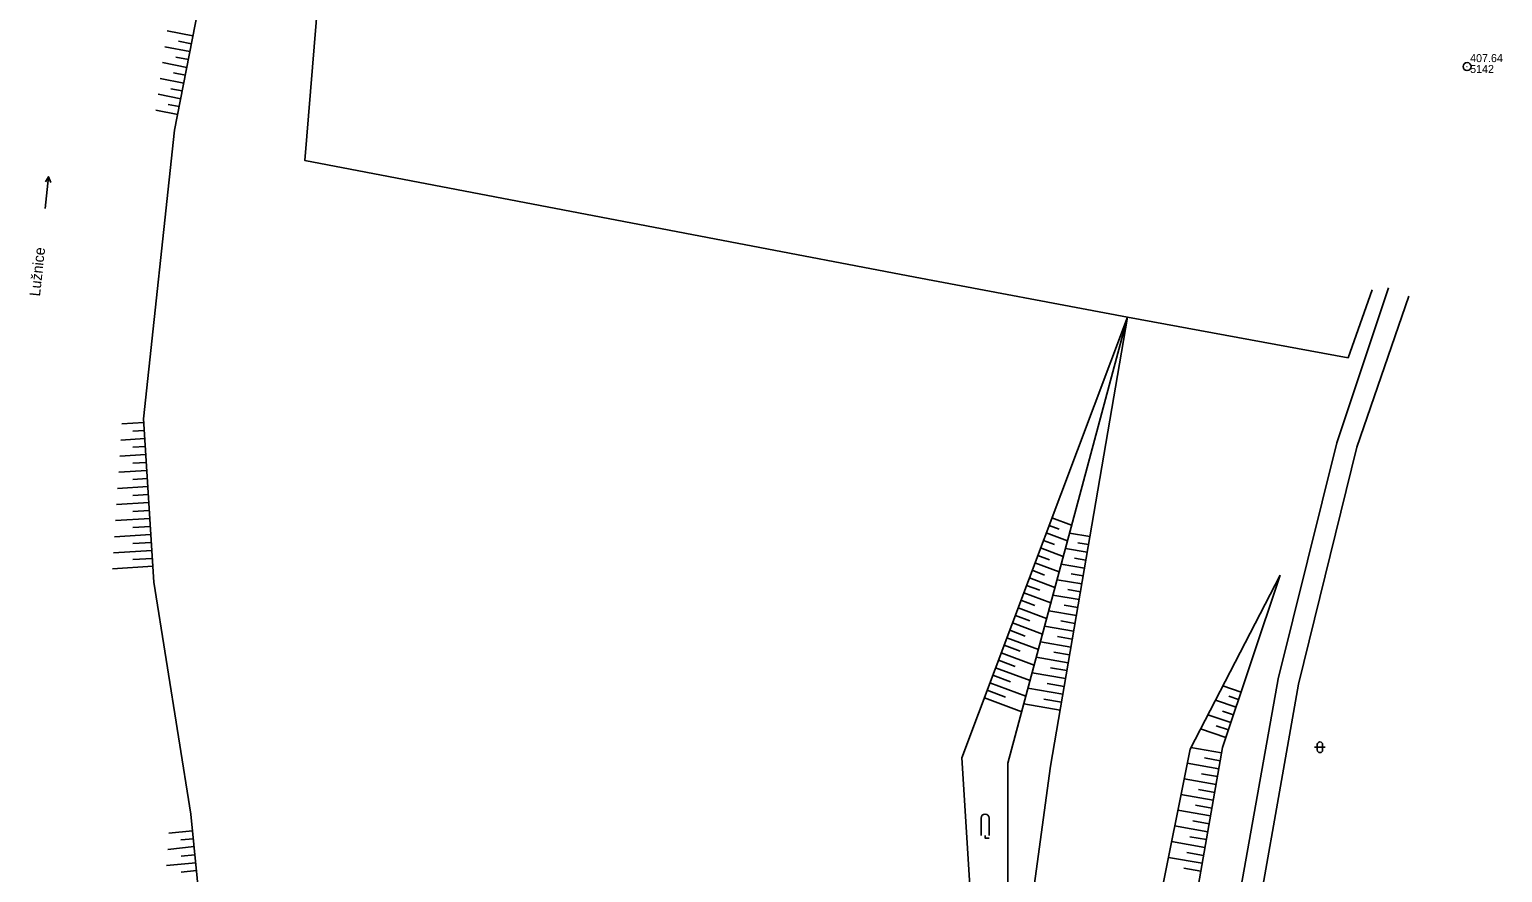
# Model space of a CAD drawing. Extents: x -737488 to -734267, y -1145775 to -1142573.
# Drawn here: x -735046 to -734907.9, y -1143003.1 to -1142924.1 of the extents above; entities that cross this region are included whole.
import ezdxf

# ---------------------------------------------------------------- set-up
doc = ezdxf.new("R2010")
doc.units = 0
for name, color, linetype in [('Vrstva 1', 7, 'Continuous'), ('Vrstva 10', 7, 'Continuous'), ('Vrstva 12', 7, 'Continuous'), ('Vrstva 13', 7, 'Continuous'), ('Vrstva 19', 7, 'Continuous'), ('Vrstva 3', 7, 'Continuous'), ('Vrstva 9', 7, 'Continuous')]:
    doc.layers.add(name, color=color, linetype=linetype)

# ---------------------------------------------------------------- blocks, each defined once
blk = doc.blocks.new('1.079')
at = {"layer": 'Vrstva 1'}
for radius in [0.75, 0.001]:
    blk.add_circle((0, -0.001), radius, dxfattribs=at)
blk = doc.blocks.new('3.100')
at = {"layer": 'Vrstva 1'}
for p, q in [((-0.75, 0), (-0.75, 3.25)), ((0.75, 0), (0.75, 3.25))]:
    blk.add_line(p, q, dxfattribs=at)
blk.add_lwpolyline([(0, 0), (0, -0.5), (0.75, -0.5)], dxfattribs=at)
blk.add_arc((0, 3.25), 0.75, 0, 180, dxfattribs=at)
blk = doc.blocks.new('3.160')
at = {"layer": 'Vrstva 1'}
for p, q in [((-1, 0), (1, 0)), ((-0.5, -0.5), (-0.5, 0.5)), ((0.5, -0.5), (0.5, 0.5))]:
    blk.add_line(p, q, dxfattribs=at)
for centre, start, end in [((0, 0.5), 0, 180), ((0, -0.5), 180, 360)]:
    blk.add_arc(centre, 0.5, start, end, dxfattribs=at)
blk = doc.blocks.new('8.021')
at = {"layer": 'Vrstva 1'}
blk.add_line((-3, 0), (3, 0), dxfattribs=at)
blk.add_lwpolyline([(2, 0.5), (3, 0), (2, -0.5)], dxfattribs=at)

msp = doc.modelspace()

# ---------------------------------------------------------------- linework, layer by layer
at = {"layer": 'Vrstva 10'}
for points in [[(-734923.42, -1142962.8), (-734918.58, -1142948.28)], [(-734916.69, -1142949.06), (-734921.55, -1142963.22)], [(-734928.93, -1142984.91), (-734923.42, -1142962.8)], [(-734921.55, -1142963.22), (-734927.04, -1142985.42)], [(-734934.2, -1143014.49), (-734928.93, -1142984.91)], [(-734927.04, -1142985.42), (-734932.25, -1143014.98)]]:
    msp.add_lwpolyline(points, dxfattribs=at)
at = {"layer": 'Vrstva 12'}
for points in [[(-735032.35, -1142933.5), (-735024.58, -1142893.71)], [(-735030.63, -1142924.67), (-735033.06, -1142924.19)], [(-735030.77, -1142925.4), (-735031.97, -1142925.17)], [(-735030.91, -1142926.14), (-735033.27, -1142925.68)], [(-735031.06, -1142926.88), (-735032.22, -1142926.65)], [(-735031.2, -1142927.61), (-735033.48, -1142927.17)], [(-735031.34, -1142928.35), (-735032.46, -1142928.13)], [(-735031.49, -1142929.08), (-735033.69, -1142928.65)], [(-735031.63, -1142929.82), (-735032.71, -1142929.61)], [(-735031.78, -1142930.56), (-735033.9, -1142930.14)], [(-735031.92, -1142931.29), (-735032.96, -1142931.09)], [(-735032.06, -1142932.03), (-735034.11, -1142931.63)], [(-735035.26, -1142960.56), (-735032.35, -1142933.5)], [(-734958.58, -1142992.32), (-734943.06, -1142951.01)], [(-734943.06, -1142951.01), (-734954.25, -1142992.81)], [(-734950.26, -1142993.11), (-734943.06, -1142951.01)], [(-735035.24, -1142960.9), (-735037.29, -1142961.03)], [(-735034.29, -1142975.87), (-735035.26, -1142960.56)], [(-735035.14, -1142962.4), (-735037.39, -1142962.54)], [(-735035.19, -1142961.65), (-735036.27, -1142961.72)], [(-735035.05, -1142963.89), (-735037.49, -1142964.05)], [(-735035.1, -1142963.15), (-735036.27, -1142963.22)], [(-735034.95, -1142965.39), (-735037.59, -1142965.56)], [(-735035, -1142964.64), (-735036.27, -1142964.72)], [(-735034.86, -1142966.89), (-735037.69, -1142967.07)], [(-735034.91, -1142966.14), (-735036.27, -1142966.23)], [(-735034.76, -1142968.39), (-735037.79, -1142968.58)], [(-735034.81, -1142967.64), (-735036.28, -1142967.73)], [(-735034.72, -1142969.13), (-735036.28, -1142969.23)], [(-735034.67, -1142969.88), (-735037.89, -1142970.09)], [(-735034.62, -1142970.63), (-735036.28, -1142970.74)], [(-734950.4, -1142970.54), (-734949.44, -1142970.9)], [(-734950.13, -1142969.84), (-734948.29, -1142970.53)], [(-735034.58, -1142971.38), (-735037.98, -1142971.6)], [(-735034.53, -1142972.13), (-735036.28, -1142972.24)], [(-734950.93, -1142971.95), (-734949.9, -1142972.33)], [(-734950.66, -1142971.24), (-734948.68, -1142971.99)], [(-734946.58, -1142971.59), (-734948.48, -1142971.26)], [(-734946.71, -1142972.32), (-734947.69, -1142972.16)], [(-735034.48, -1142972.88), (-735038.08, -1142973.1)], [(-735034.43, -1142973.63), (-735036.28, -1142973.74)], [(-734951.45, -1142973.35), (-734950.36, -1142973.76)], [(-734951.19, -1142972.65), (-734949.07, -1142973.44)], [(-734946.83, -1142973.06), (-734948.87, -1142972.72)], [(-734946.96, -1142973.8), (-734948.01, -1142973.62)], [(-735034.39, -1142974.37), (-735038.18, -1142974.61)], [(-734951.98, -1142974.75), (-734950.82, -1142975.19)], [(-734951.72, -1142974.05), (-734949.46, -1142974.9)], [(-734947.08, -1142974.54), (-734949.26, -1142974.17)], [(-734947.21, -1142975.28), (-734948.33, -1142975.09)], [(-734928.73, -1142975.2), (-734937.19, -1142991.51)], [(-734934.15, -1142991.37), (-734928.73, -1142975.2)], [(-735030.82, -1142997.59), (-735034.29, -1142975.87)], [(-734952.51, -1142976.16), (-734951.27, -1142976.62)], [(-734952.24, -1142975.46), (-734949.85, -1142976.36)], [(-734947.34, -1142976.02), (-734949.65, -1142975.63)], [(-734947.46, -1142976.76), (-734948.65, -1142976.56)], [(-734953.04, -1142977.56), (-734951.73, -1142978.05)], [(-734952.77, -1142976.86), (-734950.24, -1142977.81)], [(-734947.59, -1142977.5), (-734950.04, -1142977.08)], [(-734947.72, -1142978.24), (-734948.98, -1142978.02)], [(-734953.56, -1142978.97), (-734952.19, -1142979.48)], [(-734953.3, -1142978.26), (-734950.63, -1142979.27)], [(-734947.84, -1142978.98), (-734950.43, -1142978.54)], [(-734954.09, -1142980.37), (-734952.65, -1142980.91)], [(-734953.83, -1142979.67), (-734951.02, -1142980.72)], [(-734948.1, -1142980.46), (-734950.82, -1142979.99)], [(-734947.97, -1142979.72), (-734949.3, -1142979.49)], [(-734954.62, -1142981.77), (-734953.11, -1142982.34)], [(-734954.35, -1142981.07), (-734951.4, -1142982.18)], [(-734948.35, -1142981.94), (-734951.21, -1142981.45)], [(-734948.22, -1142981.2), (-734949.62, -1142980.96)], [(-734955.15, -1142983.18), (-734953.57, -1142983.77)], [(-734954.88, -1142982.48), (-734951.79, -1142983.64)], [(-734948.6, -1142983.41), (-734951.6, -1142982.9)], [(-734948.48, -1142982.67), (-734949.94, -1142982.42)], [(-734955.67, -1142984.58), (-734954.03, -1142985.2)], [(-734955.41, -1142983.88), (-734952.18, -1142985.09)], [(-734948.85, -1142984.89), (-734951.99, -1142984.36)], [(-734948.73, -1142984.15), (-734950.26, -1142983.89)], [(-734956.2, -1142985.99), (-734954.48, -1142986.63)], [(-734955.94, -1142985.28), (-734952.57, -1142986.55)], [(-734949.11, -1142986.37), (-734952.38, -1142985.81)], [(-734948.98, -1142985.63), (-734950.58, -1142985.36)], [(-734932.4, -1142986.16), (-734934.12, -1142985.58)], [(-734956.46, -1142986.69), (-734952.96, -1142988)], [(-734949.36, -1142987.85), (-734952.77, -1142987.27)], [(-734949.23, -1142987.11), (-734950.9, -1142986.82)], [(-734932.88, -1142987.58), (-734934.81, -1142986.93)], [(-734932.64, -1142986.87), (-734933.55, -1142986.56)], [(-734933.36, -1142989), (-734935.51, -1142988.28)], [(-734933.12, -1142988.29), (-734934.14, -1142987.95)], [(-734933.83, -1142990.42), (-734936.21, -1142989.62)], [(-734933.59, -1142989.71), (-734934.73, -1142989.33)], [(-734937.19, -1142991.51), (-734946.11, -1143036.08)], [(-734941.65, -1143034.14), (-734934.15, -1142991.37)], [(-734934.24, -1142991.86), (-734937.11, -1142991.36)], [(-734957.7, -1143006.28), (-734958.58, -1142992.32)], [(-734954.25, -1142992.81), (-734954.27, -1143006.77)], [(-734952.18, -1143007.07), (-734950.26, -1142993.11)], [(-734934.5, -1142993.34), (-734937.45, -1142992.82)], [(-734934.37, -1142992.6), (-734935.84, -1142992.34)], [(-734934.75, -1142994.82), (-734937.75, -1142994.29)], [(-734934.63, -1142994.08), (-734936.11, -1142993.82)], [(-734935.01, -1142996.3), (-734938.04, -1142995.76)], [(-734934.88, -1142995.56), (-734936.39, -1142995.29)], [(-734935.27, -1142997.77), (-734938.34, -1142997.24)], [(-734935.14, -1142997.03), (-734936.67, -1142996.77)], [(-735029.64, -1143009.61), (-735030.82, -1142997.59)], [(-734935.53, -1142999.25), (-734938.63, -1142998.71)], [(-734935.4, -1142998.51), (-734936.94, -1142998.24)], [(-735030.67, -1142999.16), (-735032.9, -1142999.38)], [(-735030.59, -1142999.91), (-735031.77, -1143000.02)], [(-734935.79, -1143000.73), (-734938.93, -1143000.18)], [(-734935.66, -1142999.99), (-734937.22, -1142999.72)], [(-735030.52, -1143000.65), (-735033, -1143000.9)], [(-735030.45, -1143001.4), (-735031.75, -1143001.53)], [(-734935.92, -1143001.47), (-734937.5, -1143001.19)], [(-735030.37, -1143002.15), (-735033.11, -1143002.41)], [(-735030.3, -1143002.89), (-735031.73, -1143003.03)], [(-734936.05, -1143002.21), (-734939.22, -1143001.65)], [(-734936.18, -1143002.94), (-734937.77, -1143002.66)]]:
    msp.add_lwpolyline(points, dxfattribs=at)
at = {"layer": 'Vrstva 9'}
msp.add_lwpolyline([(-735008.81, -1142850.65), (-735008.6, -1142854.61), (-735010.4, -1142862.01), (-735012.24, -1142865.68), (-735016.95, -1142897.52), (-735020.15, -1142936.34), (-734980.3, -1142943.95), (-734962.94, -1142947.26), (-734943.06, -1142951.01), (-734922.38, -1142954.83), (-734920.11, -1142948.45)], dxfattribs=at)

# ---------------------------------------------------------------- block references
at = {"layer": 'Vrstva 1', "xscale": 0.5, "yscale": 0.5}
msp.add_blockref('1.079', (-734911.22, -1142927.54), dxfattribs=at)
at = {"layer": 'Vrstva 3', "xscale": 0.4999999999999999, "yscale": 0.5, "rotation": 83.86187116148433}
msp.add_blockref('8.021', (-735044.32, -1142939.36), dxfattribs=at)
at = {"layer": 'Vrstva 3', "xscale": 0.5, "yscale": 0.5}
for name, p in [('3.160', (-734925.01, -1142991.34)), ('3.100', (-734956.39, -1142999.6))]:
    msp.add_blockref(name, p, dxfattribs=at)

# ---------------------------------------------------------------- texts
at = {"layer": 'Vrstva 13'}
msp.add_text('Lužnice', height=1, rotation=83.862, dxfattribs=at).set_placement((-735044.97, -1142949.11))
at = {"layer": 'Vrstva 19'}
for s, p in [(' 407.64', (-734911.22, -1142927.12)), (' 5142', (-734911.22, -1142928.14))]:
    msp.add_text(s, height=0.75, dxfattribs=at).set_placement(p)

doc.saveas('drawing.dxf')
